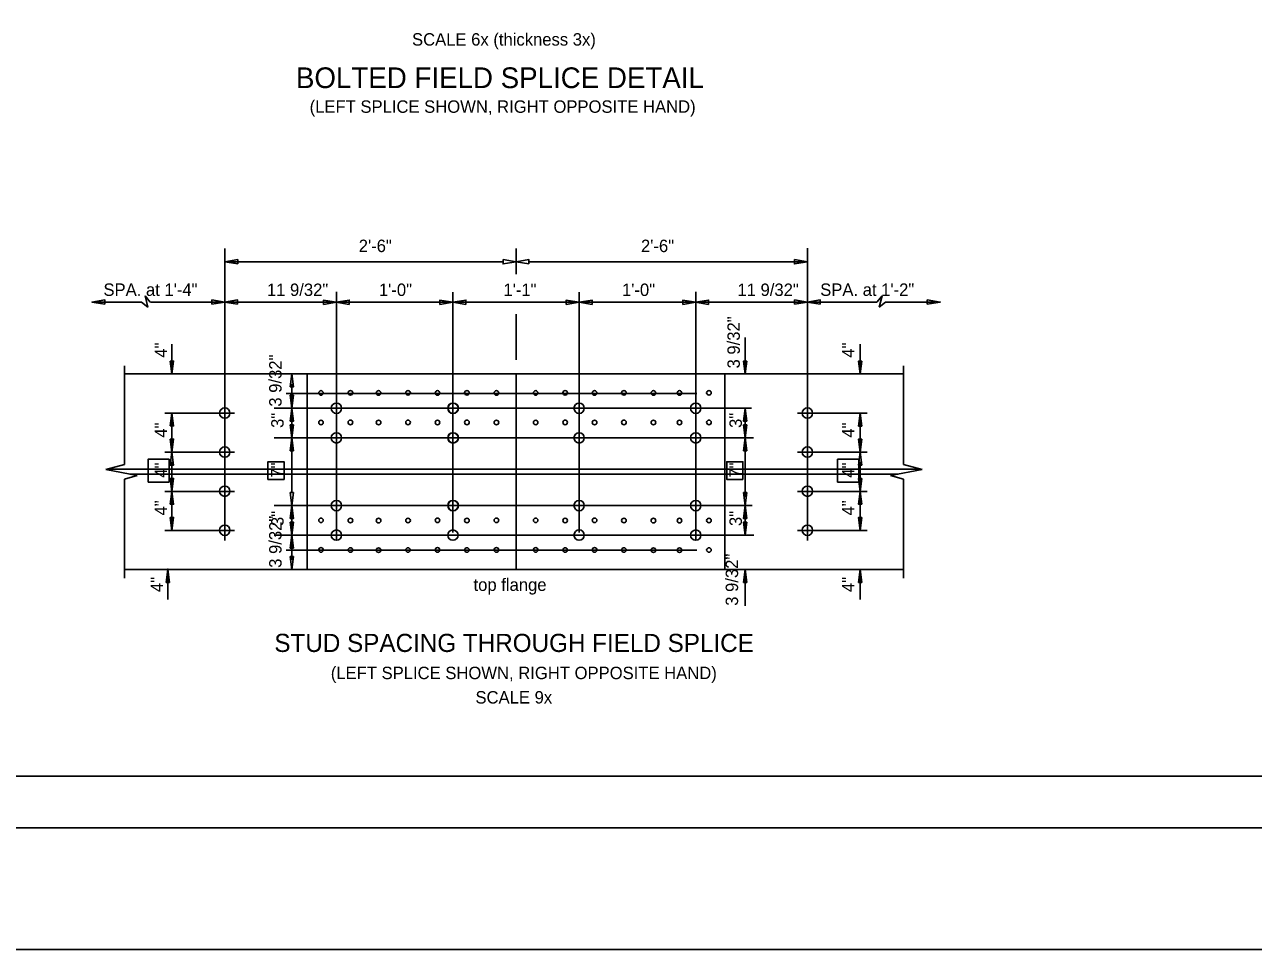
# Model space of a CAD drawing. Extents: x 4944 to 17449, y 3824 to 49087.
# Drawn here: x 13033 to 14172, y 38918 to 39775 of the extents above; entities that cross this region are included whole.
import ezdxf

# ---------------------------------------------------------------- set-up
doc = ezdxf.new("R2010")
doc.units = 0
for name, color, linetype in [('1', 7, 'Continuous'), ('2', 7, 'Continuous'), ('36_S_LINES', 7, 'Continuous'), ('37_S_TXT', 7, 'Continuous'), ('3A', 7, 'Continuous'), ('7', 7, 'Continuous'), ('BEAM', 7, 'Continuous'), ('DIM', 7, 'Continuous'), ('Level 14', 7, 'Continuous'), ('Level 25', 7, 'Continuous'), ('Level 35', 7, 'Continuous')]:
    doc.layers.add(name, color=color, linetype=linetype)

# ---------------------------------------------------------------- blocks, each defined once
blk = doc.blocks.new('4MH')
at = {"layer": 'Level 35'}
for radius, start, end in [(0.0945, 112.5426, 157.4574), (0.06, 112.5426, 157.4574), (0.06, 22.5426, 67.4574), (0.0945, 22.5426, 67.4574), (0.0945, 202.5426, 247.4574), (0.06, 202.5426, 247.4574), (0.06, 292.5426, 337.4574), (0.0945, 292.5426, 337.4574)]:
    blk.add_arc((0, 0), radius, start, end, dxfattribs=at)

msp = doc.modelspace()

# ---------------------------------------------------------------- linework, layer by layer
at = {"layer": '1'}
for centre, start, end in [((13308.2, 39433.8), 0, 180), ((13308.2, 39433.8), 180, 0), ((13335.5, 39433.9), 0, 180), ((13335.5, 39433.9), 180, 0), ((13361.6, 39433.8), 0, 180), ((13361.6, 39433.8), 180, 0), ((13388.9, 39433.9), 0, 180), ((13388.9, 39433.9), 180, 0), ((13416.2, 39433.8), 0, 180), ((13416.2, 39433.8), 180, 0), ((13443.5, 39433.9), 0, 180), ((13443.5, 39433.9), 180, 0), ((13470.8, 39433.8), 0, 180), ((13470.8, 39433.8), 180, 0), ((13507.2, 39433.8), 0, 180), ((13507.2, 39433.8), 180, 0), ((13534.5, 39433.9), 0, 180), ((13534.5, 39433.9), 180, 0), ((13561.8, 39433.8), 0, 180), ((13561.8, 39433.8), 180, 0), ((13589, 39433.9), 0, 180), ((13589, 39433.9), 180, 0), ((13616.3, 39433.8), 0, 180), ((13616.3, 39433.8), 180, 0), ((13640.5, 39433.8), 0, 180), ((13640.5, 39433.8), 180, 0), ((13667.8, 39433.9), 0, 180), ((13667.8, 39433.9), 180, 0), ((13308.2, 39406.4), 0, 180), ((13335.5, 39406.5), 0, 180), ((13361.6, 39406.4), 0, 180), ((13388.9, 39406.5), 0, 180), ((13416.2, 39406.4), 0, 180), ((13443.5, 39406.5), 0, 180), ((13470.8, 39406.4), 0, 180), ((13507.2, 39406.4), 0, 180), ((13534.5, 39406.5), 0, 180), ((13561.8, 39406.4), 0, 180), ((13589, 39406.5), 0, 180), ((13616.3, 39406.4), 0, 180), ((13640.5, 39406.4), 0, 180), ((13667.8, 39406.5), 0, 180), ((13308.2, 39406.4), 180, 0), ((13335.5, 39406.5), 180, 0), ((13361.6, 39406.4), 180, 0), ((13388.9, 39406.5), 180, 0), ((13416.2, 39406.4), 180, 0), ((13443.5, 39406.5), 180, 0), ((13470.8, 39406.4), 180, 0), ((13507.2, 39406.4), 180, 0), ((13534.5, 39406.5), 180, 0), ((13561.8, 39406.4), 180, 0), ((13589, 39406.5), 180, 0), ((13616.3, 39406.4), 180, 0), ((13640.5, 39406.4), 180, 0), ((13667.8, 39406.5), 180, 0), ((13308.2, 39315.7), 0, 180), ((13335.5, 39315.6), 0, 180), ((13361.6, 39315.5), 0, 180), ((13388.9, 39315.6), 0, 180), ((13416.2, 39315.7), 0, 180), ((13443.5, 39315.6), 0, 180), ((13470.8, 39315.7), 0, 180), ((13507.2, 39315.7), 0, 180), ((13534.5, 39315.6), 0, 180), ((13561.8, 39315.7), 0, 180), ((13589, 39315.6), 0, 180), ((13616.3, 39315.5), 0, 180), ((13640.5, 39315.5), 0, 180), ((13667.8, 39315.6), 0, 180), ((13308.2, 39315.7), 180, 0), ((13335.5, 39315.6), 180, 0), ((13361.6, 39315.5), 180, 0), ((13388.9, 39315.6), 180, 0), ((13416.2, 39315.7), 180, 0), ((13443.5, 39315.6), 180, 0), ((13470.8, 39315.7), 180, 0), ((13507.2, 39315.7), 180, 0), ((13534.5, 39315.6), 180, 0), ((13561.8, 39315.7), 180, 0), ((13589, 39315.6), 180, 0), ((13616.3, 39315.5), 180, 0), ((13640.5, 39315.5), 180, 0), ((13667.8, 39315.6), 180, 0), ((13308.2, 39288.3), 0, 180), ((13308.2, 39288.3), 180, 0), ((13335.5, 39288.2), 0, 180), ((13335.5, 39288.2), 180, 0), ((13361.6, 39288.1), 0, 180), ((13361.6, 39288.1), 180, 0), ((13388.9, 39288.2), 0, 180), ((13388.9, 39288.2), 180, 0), ((13416.2, 39288.3), 0, 180), ((13416.2, 39288.3), 180, 0), ((13443.5, 39288.2), 0, 180), ((13443.5, 39288.2), 180, 0), ((13470.8, 39288.3), 0, 180), ((13470.8, 39288.3), 180, 0), ((13507.2, 39288.3), 0, 180), ((13507.2, 39288.3), 180, 0), ((13534.5, 39288.2), 0, 180), ((13534.5, 39288.2), 180, 0), ((13561.8, 39288.3), 0, 180), ((13561.8, 39288.3), 180, 0), ((13589, 39288.2), 0, 180), ((13589, 39288.2), 180, 0), ((13616.3, 39288.1), 0, 180), ((13616.3, 39288.1), 180, 0), ((13640.5, 39288.1), 0, 180), ((13640.5, 39288.1), 180, 0), ((13667.8, 39288.2), 0, 180), ((13667.8, 39288.2), 180, 0)]:
    msp.add_arc(centre, 2.13, start, end, dxfattribs=at)
at = {"layer": '2'}
msp.add_line((13489, 39270.1), (13489, 39451.4), dxfattribs=at)
at = {"layer": '36_S_LINES'}
for p, q in [((13489, 39567.6), (13489, 39543.8)), ((13219, 39555.4), (13477, 39555.4)), ((13501, 39555.4), (13759, 39555.4)), ((13145.2, 39523.9), (13147.7, 39513.4)), ((13150, 39518), (13145.2, 39523.9)), ((13823.4, 39517.9), (13828.3, 39523.9)), ((13828.3, 39523.9), (13825.7, 39513.3)), ((13142, 39518), (13095.9, 39518)), ((13147.7, 39513.4), (13142, 39518)), ((13457.5, 39517.9), (13150.1, 39517.9)), ((13457.5, 39517.9), (13520.4, 39517.9)), ((13520.4, 39517.9), (13823.4, 39517.9)), ((13825.7, 39513.3), (13831.5, 39517.9)), ((13831.5, 39518), (13877.6, 39518)), ((13489, 39506.8), (13489, 39464.5)), ((13170, 39479.1), (13170, 39451.4)), ((13701.4, 39485.1), (13701.4, 39451.4)), ((13807.9, 39479.1), (13807.9, 39451.4)), ((13126, 39459), (13126, 39367.6)), ((13848.2, 39459), (13848.2, 39367.6)), ((13281.1, 39442.3), (13281.1, 39415.1)), ((13281.1, 39419.5), (13281.1, 39392.2)), ((13701.4, 39419.5), (13701.4, 39392.2)), ((13170, 39415.4), (13170, 39379)), ((13807.9, 39415.4), (13807.9, 39379)), ((13281.1, 39342.6), (13281.1, 39392.3)), ((13701.4, 39337.4), (13701.4, 39392.3)), ((13126, 39367.6), (13108.9, 39362.8)), ((13108.9, 39362.8), (13138, 39357.2)), ((13170, 39342.6), (13170, 39369.9)), ((13807.9, 39342.6), (13807.9, 39369.9)), ((13865.3, 39362.8), (13836.2, 39357.2)), ((13848.2, 39367.6), (13865.3, 39362.8)), ((13138, 39357.2), (13126, 39353.8)), ((13126, 39353.8), (13126, 39262.1)), ((13836.2, 39357.2), (13848.2, 39353.8)), ((13848.2, 39353.8), (13848.2, 39262.1)), ((13170, 39306.1), (13170, 39342.6)), ((13807.9, 39306.1), (13807.9, 39342.6)), ((13281.1, 39302.1), (13281.1, 39329.4)), ((13701.4, 39302.1), (13701.4, 39329.4)), ((13281.1, 39279.2), (13281.1, 39306.5)), ((13166.3, 39270.1), (13166.3, 39242.4)), ((13701.4, 39270.1), (13701.4, 39236.6)), ((13807.9, 39270.1), (13807.9, 39242.4))]:
    msp.add_line(p, q, dxfattribs=at)
for points in [[(13231, 39553.4), (13219, 39555.4), (13231, 39557.4)], [(13477, 39557.4), (13489, 39555.4), (13477, 39553.4)], [(13501, 39553.4), (13489, 39555.4), (13501, 39557.4)], [(13747, 39557.4), (13759, 39555.4), (13747, 39553.4)], [(13107.9, 39516), (13107.9, 39520), (13095.9, 39518)], [(13207.1, 39516), (13207.1, 39520), (13219.1, 39518)], [(13230.9, 39516), (13230.9, 39520), (13218.9, 39518)], [(13310.6, 39515.9), (13310.6, 39519.9), (13322.6, 39517.9)], [(13334.4, 39515.9), (13334.4, 39519.9), (13322.4, 39517.9)], [(13418.5, 39515.9), (13418.5, 39519.9), (13430.5, 39517.9)], [(13442.5, 39515.9), (13442.5, 39519.9), (13430.5, 39517.9)], [(13535.5, 39515.9), (13535.5, 39519.9), (13547.5, 39517.9)], [(13559.5, 39515.9), (13559.5, 39519.9), (13547.5, 39517.9)], [(13643.6, 39515.9), (13643.6, 39519.9), (13655.6, 39517.9)], [(13667.4, 39515.9), (13667.4, 39519.9), (13655.4, 39517.9)], [(13747.1, 39516), (13747.1, 39520), (13759.1, 39518)], [(13770.9, 39516), (13770.9, 39520), (13758.9, 39518)], [(13870.1, 39516), (13870.1, 39520), (13882.1, 39518)], [(13168.5, 39463.4), (13171.6, 39463.4), (13170, 39451.4)], [(13702.9, 39463.4), (13699.9, 39463.4), (13701.4, 39451.4)], [(13809.5, 39463.4), (13806.4, 39463.4), (13807.9, 39451.4)], [(13279.6, 39439.4), (13282.6, 39439.4), (13281.1, 39451.4)], [(13279.6, 39431.6), (13282.6, 39431.6), (13281.1, 39419.6)], [(13279.6, 39407.5), (13282.6, 39407.5), (13281.1, 39419.5)], [(13702.9, 39407.5), (13699.9, 39407.5), (13701.4, 39419.5)], [(13168.5, 39403.2), (13171.6, 39403.2), (13170, 39415.2)], [(13809.5, 39403.1), (13806.4, 39403.1), (13807.9, 39415.1)], [(13279.6, 39404.2), (13282.6, 39404.2), (13281.1, 39392.2)], [(13702.9, 39404.2), (13699.9, 39404.2), (13701.4, 39392.2)], [(13168.5, 39391), (13171.6, 39391), (13170, 39379)], [(13279.6, 39380.3), (13282.6, 39380.3), (13281.1, 39392.3)], [(13702.9, 39380.3), (13699.9, 39380.3), (13701.4, 39392.3)], [(13809.5, 39391), (13806.4, 39391), (13807.9, 39379)], [(13168.5, 39367), (13171.6, 39367), (13170, 39379)], [(13809.5, 39367), (13806.4, 39367), (13807.9, 39379)], [(13168.5, 39354.6), (13171.6, 39354.6), (13170, 39342.6)], [(13809.5, 39354.6), (13806.4, 39354.6), (13807.9, 39342.6)], [(13168.5, 39330.6), (13171.6, 39330.6), (13170, 39342.6)], [(13279.6, 39341.4), (13282.6, 39341.4), (13281.1, 39329.4)], [(13702.9, 39341.4), (13699.9, 39341.4), (13701.4, 39329.4)], [(13809.5, 39330.6), (13806.4, 39330.6), (13807.9, 39342.6)], [(13279.6, 39317.4), (13282.6, 39317.4), (13281.1, 39329.4)], [(13702.9, 39317.4), (13699.9, 39317.4), (13701.4, 39329.4)], [(13168.5, 39318.4), (13171.6, 39318.4), (13170, 39306.4)], [(13809.5, 39318.4), (13806.4, 39318.4), (13807.9, 39306.4)], [(13279.6, 39314.1), (13282.6, 39314.1), (13281.1, 39302.1)], [(13702.9, 39314.1), (13699.9, 39314.1), (13701.4, 39302.1)], [(13279.6, 39290), (13282.6, 39290), (13281.1, 39302)], [(13279.6, 39282.1), (13282.6, 39282.1), (13281.1, 39270.1)], [(13164.7, 39258.1), (13167.8, 39258.1), (13166.3, 39270.1)], [(13702.9, 39258.1), (13699.9, 39258.1), (13701.4, 39270.1)], [(13809.5, 39258.1), (13806.4, 39258.1), (13807.9, 39270.1)]]:
    msp.add_lwpolyline(points, close=True, dxfattribs=at)
at = {"layer": '37_S_TXT'}
msp.add_lwpolyline([(12345.1, 41222), (15801.2, 41222), (15801.2, 38917.9), (12345.1, 38917.9)], close=True, dxfattribs=at)
at = {"layer": '3A'}
for p, q in [((13219, 39297.1), (13219, 39567.6)), ((13759, 39297.1), (13759, 39568)), ((13322.5, 39297.1), (13322.5, 39527.6)), ((13430.5, 39304.5), (13430.5, 39527.1)), ((13547.5, 39304.5), (13547.5, 39527.1)), ((13655.5, 39297.1), (13655.5, 39527.6)), ((13707.2, 39419.6), (13264.8, 39419.6)), ((13163.5, 39415.2), (13228, 39415.2)), ((13814.5, 39415.2), (13750, 39415.2)), ((13709.1, 39392.2), (13264.8, 39392.2)), ((13163.5, 39379), (13228, 39379)), ((13814.5, 39379), (13750, 39379)), ((13163.5, 39342.6), (13228, 39342.6)), ((13814.5, 39342.6), (13750, 39342.6)), ((13708, 39329.4), (13264.8, 39329.4)), ((13163.5, 39306.4), (13228, 39306.4)), ((13814.5, 39306.4), (13750, 39306.4)), ((13709.4, 39302), (13264.8, 39302))]:
    msp.add_line(p, q, dxfattribs=at)
for points in [[(13147.9, 39351.2), (13147.9, 39372.3), (13167.4, 39372.3), (13167.4, 39351.2)], [(13259.1, 39353.6), (13259.1, 39370.1), (13274, 39370.1), (13274, 39353.6)], [(13699.2, 39353.6), (13699.2, 39370.1), (13684.3, 39370.1), (13684.3, 39353.6)], [(13806.6, 39351.2), (13806.6, 39372.3), (13787, 39372.3), (13787, 39351.2)]]:
    msp.add_lwpolyline(points, close=True, dxfattribs=at)
at = {"layer": '7'}
for p, q in [((13109.7, 39363.1), (13864.5, 39363.1)), ((13131.1, 39358.5), (13843.1, 39358.5))]:
    msp.add_line(p, q, dxfattribs=at)
at = {"layer": 'DEFPOINTS'}
for p, q in [((13275.8, 39433.4), (13656.6, 39433.4)), ((13275.8, 39288.1), (13656.6, 39288.1))]:
    msp.add_line(p, q, dxfattribs=at)
at = {"layer": 'DIM'}
msp.add_lwpolyline([(12502.3, 41142.8), (15766.4, 41142.8), (15766.4, 39030.7), (12502.3, 39030.7)], close=True, dxfattribs=at)
at = {"layer": 'Level 14'}
msp.add_lwpolyline([(15713.6, 39078.7), (12689.5, 39078.7), (12689.5, 41094.8), (15713.6, 41094.8)], close=True, dxfattribs=at)
at = {"layer": 'Level 25'}
for p, q in [((13126, 39451.4), (13848.2, 39451.4)), ((13295.5, 39270.1), (13295.5, 39451.4)), ((13682.4, 39270.1), (13682.4, 39451.4)), ((13126, 39270.1), (13848.2, 39270.1))]:
    msp.add_line(p, q, dxfattribs=at)
for centre in [(13219, 39415.2), (13322.5, 39419.6), (13430.5, 39419.6), (13430.8, 39419.6), (13547.5, 39419.6), (13655.5, 39419.6), (13759, 39415.2), (13322.5, 39392.2), (13430.5, 39392.2), (13430.8, 39392.2), (13547.5, 39392.2), (13655.5, 39392.2), (13219, 39379), (13759, 39379), (13219, 39342.7), (13759, 39342.7), (13322.5, 39329.4), (13430.5, 39329.4), (13430.8, 39329.4), (13547.5, 39329.4), (13655.5, 39329.4), (13219, 39306.5), (13322.5, 39302), (13430.5, 39302), (13547.5, 39302.1), (13655.5, 39302), (13759, 39306.5)]:
    msp.add_circle(centre, 4.79, dxfattribs=at)

# ---------------------------------------------------------------- block references
at = {"layer": 'Level 35', "xscale": 5, "yscale": 5}
msp.add_blockref('4MH', (13166.3, 39270.1), dxfattribs=at)

# ---------------------------------------------------------------- texts
at = {"layer": '3A'}
for s, p in [('(LEFT SPLICE SHOWN, RIGHT OPPOSITE HAND)', (13297.7, 39693.5)), ('2\'-6"', (13343.2, 39564.4)), ('2\'-6"', (13604.8, 39564.4)), ('SPA. at 1\'-4"', (13106.6, 39523.8)), ('11 9/32"', (13258.1, 39523.7)), ('1\'-0"', (13361.9, 39523.7)), ('1\'-1"', (13477.3, 39523.7)), ('1\'-0"', (13587.2, 39523.7)), ('11 9/32"', (13694.2, 39523.7)), ('SPA. at 1\'-2"', (13770.9, 39523.8)), ('(LEFT SPLICE SHOWN, RIGHT OPPOSITE HAND)', (13317.3, 39168.5))]:
    msp.add_text(s, height=11.52, dxfattribs=at).set_placement(p)
for s, p in [('3 9/32"', (13696.4, 39456.5)), ('4"', (13165.6, 39466.5)), ('4"', (13802.6, 39466.5)), ('3 9/32"', (13271.7, 39421.1)), ('3"', (13273.6, 39401.4)), ('3"', (13698.3, 39401.4)), ('4"', (13165.6, 39392.4)), ('4"', (13802.6, 39392.4)), ('4"', (13165.6, 39355.2)), ('7"', (13273.4, 39355.3)), ('7"', (13698.3, 39355.3)), ('4"', (13802.6, 39355.2)), ('4"', (13165.6, 39320.2)), ('4"', (13802.6, 39320.2)), ('3 9/32"', (13271.7, 39271.7)), ('3"', (13273.6, 39310.4)), ('3"', (13698.3, 39310.4)), ('3 9/32"', (13694.8, 39236.5)), ('4"', (13161.8, 39249.2)), ('4"', (13802.6, 39249.2))]:
    msp.add_text(s, height=11.52, rotation=90, dxfattribs=at).set_placement(p)
at = {"layer": 'BEAM'}
for s, height, p in [('BOLTED FIELD SPLICE DETAIL', 19.2, (13285, 39716.4)), ('STUD SPACING THROUGH FIELD SPLICE', 16.8, (13265, 39193.7))]:
    msp.add_text(s, height=height, dxfattribs=at).set_placement(p)
at = {"layer": 'DEFPOINTS'}
for s, p in [('SCALE 6x (thickness 3x)', (13392.6, 39755.8)), ('top flange', (13449.6, 39250.3)), ('SCALE 9x', (13451.4, 39145.9))]:
    msp.add_text(s, height=11.52, dxfattribs=at).set_placement(p)

doc.saveas('drawing.dxf')
